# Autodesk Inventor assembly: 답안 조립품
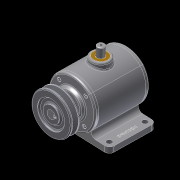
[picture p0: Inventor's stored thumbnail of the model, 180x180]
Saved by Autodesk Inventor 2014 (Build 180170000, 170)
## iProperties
Created: 2015-08
Part Number: 답안 조립품
Document SubType Name: Assembly
Designer: USER
Author: USER
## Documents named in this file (14)
- C:\Users\USER\Desktop\350805V1033\답안 조립품.iam
- C:\Users\USER\Desktop\350805V1033\본체.ipt
- C:\Users\USER\Desktop\350805V1033\베어링 6203.ipt
- C:\Users\USER\Desktop\350805V1033\뒷커버.ipt
- C:\Users\USER\Desktop\350805V1033\M4-소켓머리.ipt
- C:\Users\USER\Desktop\350805V1033\축.ipt
- C:\Users\USER\Desktop\350805V1033\앞커버.ipt
- C:\Users\USER\Desktop\350805V1033\오일실.ipt
- C:\Users\USER\Desktop\350805V1033\KS B 1028  - 납작점M4x5.ipt
- C:\Users\USER\Desktop\350805V1033\KS B 1311 - 5 x 5 x 18I.ipt
- C:\Users\USER\Desktop\350805V1033\V-벨트풀리.ipt
- C:\Users\USER\Desktop\350805V1033\부시.ipt
- C:\Users\USER\Desktop\350805V1033\슬라이더.ipt
- C:\Users\USER\Desktop\350805V1033\스프링.ipt
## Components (14 placed, 6 different names)
1. 7-베어링 6203:1
2. 9-M4-소켓머리:1
3. 9-M4-소켓머리:2
4. 9-M4-소켓머리:3
5. 9-M4-소켓머리:4
6. KS B 1028 납작점 - 미터 납작점M4x5:1
7. KS B 1311 (I) 5 x 5 x 18:1
8. 7-베어링 6203:2
9. 9-M4-소켓머리:5
10. 9-M4-소켓머리:6
11. 9-M4-소켓머리:7
12. 9-M4-소켓머리:8
13. 8-오일실:1
14. V-벨트풀리:1
